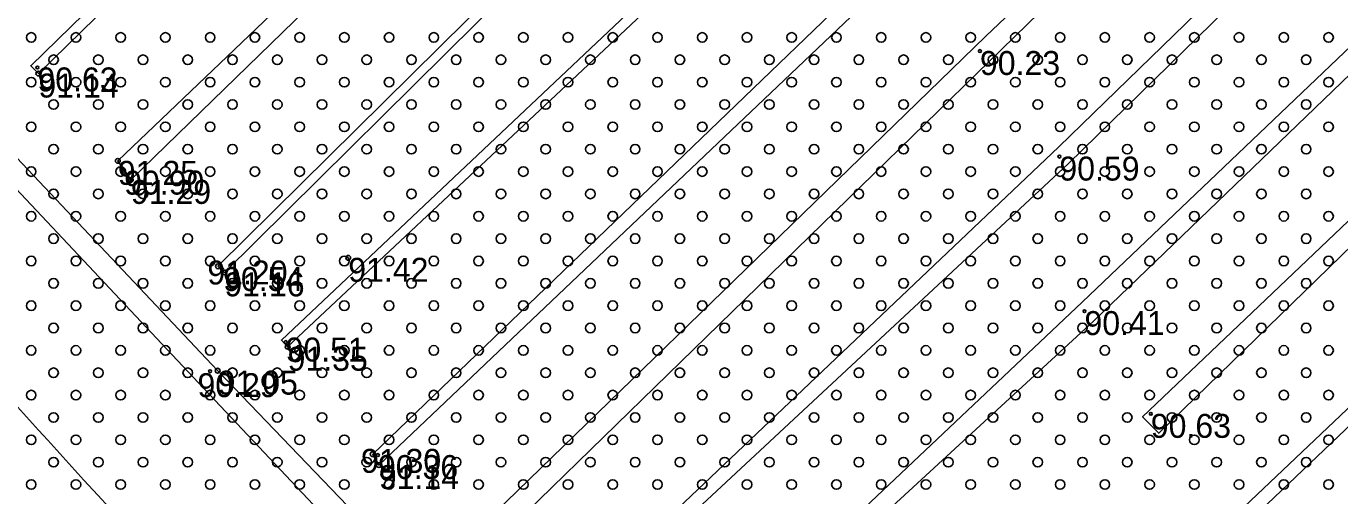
# Model space of a CAD drawing. Extents: x 316000 to 728450, y 314368 to 726000.
# Drawn here: x 725766.2 to 725971.8, y 315159.2 to 315232.8 of the extents above; entities that cross this region are included whole.
import ezdxf

# ---------------------------------------------------------------- set-up
doc = ezdxf.new("R2010")
doc.units = 0
for name, color, linetype in [('HIDG_ELEM_####_####_#', 7, 'Continuous'), ('HIDG_GRAV_####_####_#', 7, 'Continuous'), ('RELJ_AATZ_####_TKST_#', 7, 'Continuous'), ('RELJ_ELEM_####_####_#', 7, 'Continuous'), ('RELJ_HORZ_PAMT_####_#', 7, 'Continuous'), ('RELJ_NOGA_####_####_#', 7, 'Continuous'), ('TERT_ELEM_####_####_#', 7, 'Continuous'), ('TERT_KONT_####_####_#', 7, 'Continuous')]:
    doc.layers.add(name, color=color, linetype=linetype)

msp = doc.modelspace()

# ---------------------------------------------------------------- linework, layer by layer
at = {"layer": 'HIDG_ELEM_####_####_#'}
for centre in [(725915.45, 315228.87), (725767.97, 315226.3), (725927.88, 315212.34), (725781.54, 315210.14), (725796.85, 315194.72), (725931.81, 315188.15), (725806.83, 315183.31), (725794.98, 315178.73), (725942.19, 315172.06), (725821.26, 315165.61)]:
    msp.add_circle(centre, 0.225, dxfattribs=at)
at = {"layer": 'HIDG_GRAV_####_####_#'}
for points in [[(725550.64, 315437.37), (725654.91, 315324.09), (725793.17, 315176.93), (726030.02, 314925.45), (726035.1, 314929.94), (725796.17, 315178.83)], [(725944.12, 315399.45), (725945.08, 315398.33), (725768.12, 315225.34), (725766.93, 315226.56), (725944.12, 315399.45)], [(725955.19, 315378.49), (725956.23, 315377.56), (725782.6, 315208.69), (725780.55, 315211.67), (725955.19, 315378.49)], [(725973.74, 315370.77), (725974.8, 315370.03), (725797.23, 315194.21), (725796.21, 315195.17), (725973.74, 315370.77)], [(725987.03, 315355.74), (725987.76, 315354.63), (725889.4, 315259.86), (725807.12, 315182.57), (725806.14, 315183.61), (725888.9, 315261.77), (725987.03, 315355.74)], [(726007.2, 315345.16), (726007.92, 315344.37), (725904.61, 315243.16), (725821.4, 315164.04), (725820.43, 315165.74), (725902.95, 315245.17), (726007.2, 315345.16)], [(725655.9, 315327.28), (725718.48, 315261.22), (725796.17, 315178.83)], [(726013.86, 315323.76), (726014.55, 315322.37), (725916.94, 315227.27), (725836.4, 315148.81), (725834.15, 315151.37), (725916.39, 315231.21), (726013.86, 315323.76)], [(726026.72, 315310.03), (726028.38, 315308.12), (725929.27, 315211.22), (725849.42, 315136.82), (725847.67, 315137.8), (725927.82, 315213.86), (726026.72, 315310.03)], [(726041.22, 315294.28), (726042.74, 315292.12), (725933.2, 315186.57), (725862.99, 315121.84), (725861.5, 315123.44), (725931.43, 315189.54), (726041.22, 315294.28)], [(726054.58, 315279.91), (726055.6, 315278.2), (725943.43, 315169.03), (725940.91, 315171.62), (726054.58, 315279.91)], [(726067.39, 315262.47), (726068.58, 315261.15), (725954.8, 315152.62), (725890.85, 315090.51), (725889.28, 315091.99), (725953.78, 315154.65), (726067.39, 315262.47)]]:
    msp.add_lwpolyline(points, dxfattribs=at)
at = {"layer": 'RELJ_ELEM_####_####_#'}
for centre in [(725768.12, 315225.34), (725780.55, 315211.67), (725782.6, 315208.69), (725796.21, 315195.17), (725816.61, 315196.49), (725797.23, 315194.21), (725807.12, 315182.57), (725796.17, 315178.83), (725820.43, 315165.74), (725821.4, 315164.04)]:
    msp.add_circle(centre, 0.375, dxfattribs=at)
at = {"layer": 'RELJ_HORZ_PAMT_####_#'}
for points in [[(726116.34, 315699.09), (726105.94, 315702.69), (726040.13, 315715), (725990.82, 315710.42), (725942.03, 315708.25), (725920.28, 315706.77), (725880.37, 315714.51), (725859.05, 315708.68), (725859.05, 315672.66), (725851.26, 315613.97), (725853.47, 315568.9), (725841, 315555.79), (725885.56, 315509.63), (725935.94, 315461.49), (725983.42, 315406.25), (726032.86, 315360.51), (726082.85, 315311.19), (726122.23, 315248.76), (726137.05, 315229.29), (726180.19, 315183.1), (726194.52, 315168.27), (726211.91, 315146.93), (726212.51, 315143.16)], [(726081.57, 315247.05), (726057.5, 315241.5), (726036.5, 315213.5), (725977, 315161), (725966.5, 315108.5), (725903.5, 315045.5), (725862.12, 315076.6), (725805.5, 315130), (725759.7, 315178.88), (725709.89, 315228.8), (725646.99, 315287.19), (725634.68, 315314.96), (725629.04, 315327.48), (725557.35, 315340.26), (725478.3, 315344.16)]]:
    msp.add_spline(points, degree=3, dxfattribs=at)
at = {"layer": 'RELJ_NOGA_####_####_#'}
for points in [[(726259.12, 315084.51), (726262.72, 315089.26), (726261.56, 315090.84), (726260.2, 315092.42), (726257.29, 315095.53), (726218.91, 315136.38), (726180.31, 315176.84), (726128.67, 315229.97), (726063.7, 315298.11), (725999.9, 315366.09), (725937.21, 315432.09), (725876.35, 315495.23), (725810.58, 315563.08), (725744.7, 315632.91)], [(725740.86, 315626.98), (725805.54, 315558.12), (725870.39, 315491.15), (725932.8, 315426.8), (725994.98, 315360.84), (726059.66, 315292.12), (726075.75, 315275.46), (726092.08, 315259.04), (726108.47, 315242.67), (726124.69, 315226.14), (726193.27, 315154.03), (726250.06, 315092.6), (726256.32, 315085.83), (726258.82, 315084.29), (726259.12, 315084.51)]]:
    msp.add_spline(points, degree=3, dxfattribs=at)
at = {"layer": 'TERT_ELEM_####_####_#'}
for centre in [(725767, 315231), (725774, 315231), (725781, 315231), (725788, 315231), (725795, 315231), (725802, 315231), (725809, 315231), (725816, 315231), (725823, 315231), (725830, 315231), (725837, 315231), (725844, 315231), (725851, 315231), (725858, 315231), (725865, 315231), (725872, 315231), (725879, 315231), (725886, 315231), (725893, 315231), (725900, 315231), (725907, 315231), (725914, 315231), (725921, 315231), (725928, 315231), (725935, 315231), (725942, 315231), (725949, 315231), (725956, 315231), (725963, 315231), (725970, 315231), (725770.5, 315227.5), (725777.5, 315227.5), (725784.5, 315227.5), (725791.5, 315227.5), (725798.5, 315227.5), (725805.5, 315227.5), (725812.5, 315227.5), (725819.5, 315227.5), (725826.5, 315227.5), (725833.5, 315227.5), (725840.5, 315227.5), (725847.5, 315227.5), (725854.5, 315227.5), (725861.5, 315227.5), (725868.5, 315227.5), (725875.5, 315227.5), (725882.5, 315227.5), (725889.5, 315227.5), (725896.5, 315227.5), (725903.5, 315227.5), (725910.5, 315227.5), (725917.5, 315227.5), (725924.5, 315227.5), (725931.5, 315227.5), (725938.5, 315227.5), (725945.5, 315227.5), (725952.5, 315227.5), (725959.5, 315227.5), (725966.5, 315227.5), (725767, 315224), (725774, 315224), (725781, 315224), (725788, 315224), (725795, 315224), (725802, 315224), (725809, 315224), (725816, 315224), (725823, 315224), (725830, 315224), (725837, 315224), (725844, 315224), (725851, 315224), (725858, 315224), (725865, 315224), (725872, 315224), (725879, 315224), (725886, 315224), (725893, 315224), (725900, 315224), (725907, 315224), (725914, 315224), (725921, 315224), (725928, 315224), (725935, 315224), (725942, 315224), (725949, 315224), (725956, 315224), (725963, 315224), (725970, 315224), (725770.5, 315220.5), (725777.5, 315220.5), (725784.5, 315220.5), (725791.5, 315220.5), (725798.5, 315220.5), (725805.5, 315220.5), (725812.5, 315220.5), (725819.5, 315220.5), (725826.5, 315220.5), (725833.5, 315220.5), (725840.5, 315220.5), (725847.5, 315220.5), (725854.5, 315220.5), (725861.5, 315220.5), (725868.5, 315220.5), (725875.5, 315220.5), (725882.5, 315220.5), (725889.5, 315220.5), (725896.5, 315220.5), (725903.5, 315220.5), (725910.5, 315220.5), (725917.5, 315220.5), (725924.5, 315220.5), (725931.5, 315220.5), (725938.5, 315220.5), (725945.5, 315220.5), (725952.5, 315220.5), (725959.5, 315220.5), (725966.5, 315220.5), (725767, 315217), (725774, 315217), (725781, 315217), (725788, 315217), (725795, 315217), (725802, 315217), (725809, 315217), (725816, 315217), (725823, 315217), (725830, 315217), (725837, 315217), (725844, 315217), (725851, 315217), (725858, 315217), (725865, 315217), (725872, 315217), (725879, 315217), (725886, 315217), (725893, 315217), (725900, 315217), (725907, 315217), (725914, 315217), (725921, 315217), (725928, 315217), (725935, 315217), (725942, 315217), (725949, 315217), (725956, 315217), (725963, 315217), (725970, 315217), (725770.5, 315213.5), (725777.5, 315213.5), (725784.5, 315213.5), (725791.5, 315213.5), (725798.5, 315213.5), (725805.5, 315213.5), (725812.5, 315213.5), (725819.5, 315213.5), (725826.5, 315213.5), (725833.5, 315213.5), (725840.5, 315213.5), (725847.5, 315213.5), (725854.5, 315213.5), (725861.5, 315213.5), (725868.5, 315213.5), (725875.5, 315213.5), (725882.5, 315213.5), (725889.5, 315213.5), (725896.5, 315213.5), (725903.5, 315213.5), (725910.5, 315213.5), (725917.5, 315213.5), (725924.5, 315213.5), (725931.5, 315213.5), (725938.5, 315213.5), (725945.5, 315213.5), (725952.5, 315213.5), (725959.5, 315213.5), (725966.5, 315213.5), (725767, 315210), (725774, 315210), (725781, 315210), (725788, 315210), (725795, 315210), (725802, 315210), (725809, 315210), (725816, 315210), (725823, 315210), (725830, 315210), (725837, 315210), (725844, 315210), (725851, 315210), (725858, 315210), (725865, 315210), (725872, 315210), (725879, 315210), (725886, 315210), (725893, 315210), (725900, 315210), (725907, 315210), (725914, 315210), (725921, 315210), (725928, 315210), (725935, 315210), (725942, 315210), (725949, 315210), (725956, 315210), (725963, 315210), (725970, 315210), (725770.5, 315206.5), (725777.5, 315206.5), (725784.5, 315206.5), (725791.5, 315206.5), (725798.5, 315206.5), (725805.5, 315206.5), (725812.5, 315206.5), (725819.5, 315206.5), (725826.5, 315206.5), (725833.5, 315206.5), (725840.5, 315206.5), (725847.5, 315206.5), (725854.5, 315206.5), (725861.5, 315206.5), (725868.5, 315206.5), (725875.5, 315206.5), (725882.5, 315206.5), (725889.5, 315206.5), (725896.5, 315206.5), (725903.5, 315206.5), (725910.5, 315206.5), (725917.5, 315206.5), (725924.5, 315206.5), (725931.5, 315206.5), (725938.5, 315206.5), (725945.5, 315206.5), (725952.5, 315206.5), (725959.5, 315206.5), (725966.5, 315206.5), (725767, 315203), (725774, 315203), (725781, 315203), (725788, 315203), (725795, 315203), (725802, 315203), (725809, 315203), (725816, 315203), (725823, 315203), (725830, 315203), (725837, 315203), (725844, 315203), (725851, 315203), (725858, 315203), (725865, 315203), (725872, 315203), (725879, 315203), (725886, 315203), (725893, 315203), (725900, 315203), (725907, 315203), (725914, 315203), (725921, 315203), (725928, 315203), (725935, 315203), (725942, 315203), (725949, 315203), (725956, 315203), (725963, 315203), (725970, 315203), (725770.5, 315199.5), (725777.5, 315199.5), (725784.5, 315199.5), (725791.5, 315199.5), (725798.5, 315199.5), (725805.5, 315199.5), (725812.5, 315199.5), (725819.5, 315199.5), (725826.5, 315199.5), (725833.5, 315199.5), (725840.5, 315199.5), (725847.5, 315199.5), (725854.5, 315199.5), (725861.5, 315199.5), (725868.5, 315199.5), (725875.5, 315199.5), (725882.5, 315199.5), (725889.5, 315199.5), (725896.5, 315199.5), (725903.5, 315199.5), (725910.5, 315199.5), (725917.5, 315199.5), (725924.5, 315199.5), (725931.5, 315199.5), (725938.5, 315199.5), (725945.5, 315199.5), (725952.5, 315199.5), (725959.5, 315199.5), (725966.5, 315199.5), (725767, 315196), (725774, 315196), (725781, 315196), (725788, 315196), (725795, 315196), (725802, 315196), (725809, 315196), (725816, 315196), (725823, 315196), (725830, 315196), (725837, 315196), (725844, 315196), (725851, 315196), (725858, 315196), (725865, 315196), (725872, 315196), (725879, 315196), (725886, 315196), (725893, 315196), (725900, 315196), (725907, 315196), (725914, 315196), (725921, 315196), (725928, 315196), (725935, 315196), (725942, 315196), (725949, 315196), (725956, 315196), (725963, 315196), (725970, 315196), (725770.5, 315192.5), (725777.5, 315192.5), (725784.5, 315192.5), (725791.5, 315192.5), (725798.5, 315192.5), (725805.5, 315192.5), (725812.5, 315192.5), (725819.5, 315192.5), (725826.5, 315192.5), (725833.5, 315192.5), (725840.5, 315192.5), (725847.5, 315192.5), (725854.5, 315192.5), (725861.5, 315192.5), (725868.5, 315192.5), (725875.5, 315192.5), (725882.5, 315192.5), (725889.5, 315192.5), (725896.5, 315192.5), (725903.5, 315192.5), (725910.5, 315192.5), (725917.5, 315192.5), (725924.5, 315192.5), (725931.5, 315192.5), (725938.5, 315192.5), (725945.5, 315192.5), (725952.5, 315192.5), (725959.5, 315192.5), (725966.5, 315192.5), (725767, 315189), (725774, 315189), (725781, 315189), (725788, 315189), (725795, 315189), (725802, 315189), (725809, 315189), (725816, 315189), (725823, 315189), (725830, 315189), (725837, 315189), (725844, 315189), (725851, 315189), (725858, 315189), (725865, 315189), (725872, 315189), (725879, 315189), (725886, 315189), (725893, 315189), (725900, 315189), (725907, 315189), (725914, 315189), (725921, 315189), (725928, 315189), (725935, 315189), (725942, 315189), (725949, 315189), (725956, 315189), (725963, 315189), (725970, 315189), (725770.5, 315185.5), (725777.5, 315185.5), (725784.5, 315185.5), (725791.5, 315185.5), (725798.5, 315185.5), (725805.5, 315185.5), (725812.5, 315185.5), (725819.5, 315185.5), (725826.5, 315185.5), (725833.5, 315185.5), (725840.5, 315185.5), (725847.5, 315185.5), (725854.5, 315185.5), (725861.5, 315185.5), (725868.5, 315185.5), (725875.5, 315185.5), (725882.5, 315185.5), (725889.5, 315185.5), (725896.5, 315185.5), (725903.5, 315185.5), (725910.5, 315185.5), (725917.5, 315185.5), (725924.5, 315185.5), (725931.5, 315185.5), (725938.5, 315185.5), (725945.5, 315185.5), (725952.5, 315185.5), (725959.5, 315185.5), (725966.5, 315185.5), (725767, 315182), (725774, 315182), (725781, 315182), (725788, 315182), (725795, 315182), (725802, 315182), (725809, 315182), (725816, 315182), (725823, 315182), (725830, 315182), (725837, 315182), (725844, 315182), (725851, 315182), (725858, 315182), (725865, 315182), (725872, 315182), (725879, 315182), (725886, 315182), (725893, 315182), (725900, 315182), (725907, 315182), (725914, 315182), (725921, 315182), (725928, 315182), (725935, 315182), (725942, 315182), (725949, 315182), (725956, 315182), (725963, 315182), (725970, 315182), (725770.5, 315178.5), (725777.5, 315178.5), (725784.5, 315178.5), (725791.5, 315178.5), (725798.5, 315178.5), (725805.5, 315178.5), (725812.5, 315178.5), (725819.5, 315178.5), (725826.5, 315178.5), (725833.5, 315178.5), (725840.5, 315178.5), (725847.5, 315178.5), (725854.5, 315178.5), (725861.5, 315178.5), (725868.5, 315178.5), (725875.5, 315178.5), (725882.5, 315178.5), (725889.5, 315178.5), (725896.5, 315178.5), (725903.5, 315178.5), (725910.5, 315178.5), (725917.5, 315178.5), (725924.5, 315178.5), (725931.5, 315178.5), (725938.5, 315178.5), (725945.5, 315178.5), (725952.5, 315178.5), (725959.5, 315178.5), (725966.5, 315178.5), (725767, 315175), (725774, 315175), (725781, 315175), (725788, 315175), (725795, 315175), (725802, 315175), (725809, 315175), (725816, 315175), (725823, 315175), (725830, 315175), (725837, 315175), (725844, 315175), (725851, 315175), (725858, 315175), (725865, 315175), (725872, 315175), (725879, 315175), (725886, 315175), (725893, 315175), (725900, 315175), (725907, 315175), (725914, 315175), (725921, 315175), (725928, 315175), (725935, 315175), (725942, 315175), (725949, 315175), (725956, 315175), (725963, 315175), (725970, 315175), (725770.5, 315171.5), (725777.5, 315171.5), (725784.5, 315171.5), (725791.5, 315171.5), (725798.5, 315171.5), (725805.5, 315171.5), (725812.5, 315171.5), (725819.5, 315171.5), (725826.5, 315171.5), (725833.5, 315171.5), (725840.5, 315171.5), (725847.5, 315171.5), (725854.5, 315171.5), (725861.5, 315171.5), (725868.5, 315171.5), (725875.5, 315171.5), (725882.5, 315171.5), (725889.5, 315171.5), (725896.5, 315171.5), (725903.5, 315171.5), (725910.5, 315171.5), (725917.5, 315171.5), (725924.5, 315171.5), (725931.5, 315171.5), (725938.5, 315171.5), (725945.5, 315171.5), (725952.5, 315171.5), (725959.5, 315171.5), (725966.5, 315171.5), (725767, 315168), (725774, 315168), (725781, 315168), (725788, 315168), (725795, 315168), (725802, 315168), (725809, 315168), (725816, 315168), (725823, 315168), (725830, 315168), (725837, 315168), (725844, 315168), (725851, 315168), (725858, 315168), (725865, 315168), (725872, 315168), (725879, 315168), (725886, 315168), (725893, 315168), (725900, 315168), (725907, 315168), (725914, 315168), (725921, 315168), (725928, 315168), (725935, 315168), (725942, 315168), (725949, 315168), (725956, 315168), (725963, 315168), (725970, 315168), (725770.5, 315164.5), (725777.5, 315164.5), (725784.5, 315164.5), (725791.5, 315164.5), (725798.5, 315164.5), (725805.5, 315164.5), (725812.5, 315164.5), (725819.5, 315164.5), (725826.5, 315164.5), (725833.5, 315164.5), (725840.5, 315164.5), (725847.5, 315164.5), (725854.5, 315164.5), (725861.5, 315164.5), (725868.5, 315164.5), (725875.5, 315164.5), (725882.5, 315164.5), (725889.5, 315164.5), (725896.5, 315164.5), (725903.5, 315164.5), (725910.5, 315164.5), (725917.5, 315164.5), (725924.5, 315164.5), (725931.5, 315164.5), (725938.5, 315164.5), (725945.5, 315164.5), (725952.5, 315164.5), (725959.5, 315164.5), (725966.5, 315164.5), (725767, 315161), (725774, 315161), (725781, 315161), (725788, 315161), (725795, 315161), (725802, 315161), (725809, 315161), (725816, 315161), (725823, 315161), (725830, 315161), (725837, 315161), (725844, 315161), (725851, 315161), (725858, 315161), (725865, 315161), (725872, 315161), (725879, 315161), (725886, 315161), (725893, 315161), (725900, 315161), (725907, 315161), (725914, 315161), (725921, 315161), (725928, 315161), (725935, 315161), (725942, 315161), (725949, 315161), (725956, 315161), (725963, 315161), (725970, 315161)]:
    msp.add_circle(centre, 0.75, dxfattribs=at)
at = {"layer": 'TERT_KONT_####_####_#'}
msp.add_spline([(726171.05, 315177.78), (726060.22, 315058.34), (726046.85, 314926.57), (725966, 314840.49), (725918.95, 314808.85), (725841.04, 314808.85), (725695.46, 314898.17)], degree=3, dxfattribs=at)

# ---------------------------------------------------------------- texts
at = {"layer": 'RELJ_AATZ_####_TKST_#'}
for s, p in [('90.23', (725915.45, 315225.12)), ('90.63', (725767.97, 315222.55)), ('91.14', (725768.12, 315221.59)), ('90.59', (725927.88, 315208.59)), ('91.25', (725780.55, 315207.92)), ('90.90', (725781.54, 315206.39)), ('91.29', (725782.6, 315204.94)), ('91.20', (725794.56, 315192.32)), ('91.42', (725816.61, 315192.74)), ('90.54', (725797.02, 315191.3)), ('91.16', (725797.23, 315190.46)), ('90.41', (725931.81, 315184.4)), ('90.51', (725806.8, 315180.26)), ('91.35', (725807.12, 315178.82)), ('90.29', (725793.02, 315174.68)), ('91.05', (725796.17, 315175.08)), ('90.63', (725942.19, 315168.31)), ('91.30', (725818.6, 315162.83)), ('90.36', (725821.26, 315161.86)), ('91.14', (725821.4, 315160.29))]:
    msp.add_text(s, height=3.75, dxfattribs=at).set_placement(p)

doc.saveas('drawing.dxf')
